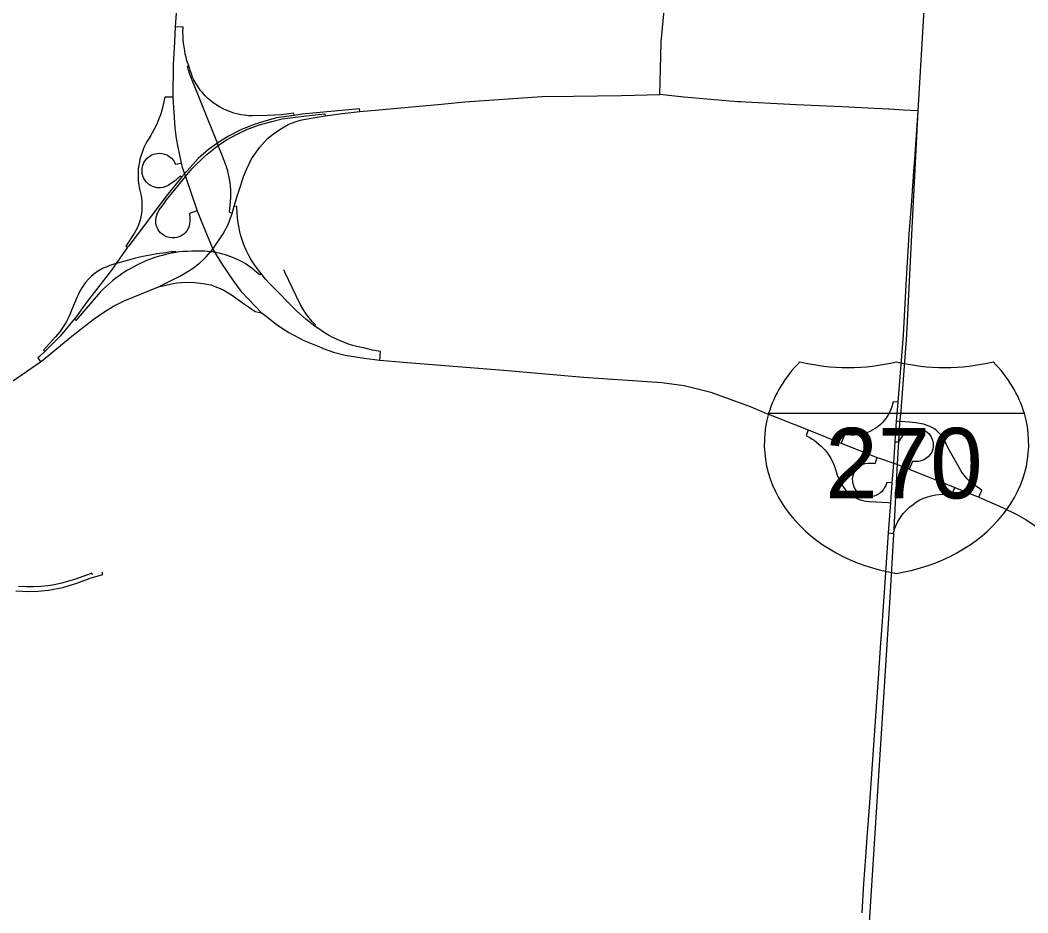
# Model space of a CAD drawing. Extents: x -1146 to -445, y -1283 to -822.
# Drawn here: x -822.31 to -786.59, y -1035.57 to -1003.92 of the extents above; entities that cross this region are included whole.
import ezdxf

# ---------------------------------------------------------------- set-up
doc = ezdxf.new("R2010")
doc.units = 0
for name, color, linetype in [('GM_X_Interchange_Ramps', 7, 'Continuous'), ('GM_X_Interstate_Route', 7, 'Continuous'), ('GM_X_Interstate_Shield', 7, 'Continuous'), ('GM_X_State_Route', 7, 'Continuous'), ('GM_X_Township', 7, 'Continuous'), ('GM_X_US_Route', 7, 'Continuous')]:
    doc.layers.add(name, color=color, linetype=linetype)

msp = doc.modelspace()

# ---------------------------------------------------------------- linework, layer by layer
at = {"layer": 'GM_X_Interchange_Ramps'}
for points in [[(-812.59, -1007.298), (-812.601, -1007.222), (-813.047, -1007.28), (-813.536, -1007.297), (-814.066, -1007.313), (-814.216, -1007.309), (-814.35, -1007.296), (-814.488, -1007.276), (-814.632, -1007.244), (-814.735, -1007.216), (-814.857, -1007.176), (-815.002, -1007.119), (-815.09, -1007.078), (-815.241, -1006.998), (-815.371, -1006.917), (-815.467, -1006.848), (-815.566, -1006.77), (-815.663, -1006.684), (-815.747, -1006.602), (-815.846, -1006.493), (-815.922, -1006.399), (-816.002, -1006.287), (-816.071, -1006.179), (-816.146, -1006.044), (-816.195, -1005.941), (-816.238, -1005.825), (-816.281, -1005.703), (-816.308, -1005.618), (-816.329, -1005.548), (-816.332, -1005.539), (-816.394, -1005.363), (-816.428, -1005.238), (-816.453, -1005.124), (-816.476, -1005.008), (-816.499, -1004.868), (-816.517, -1004.74), (-816.529, -1004.608), (-816.534, -1004.494), (-816.536, -1004.35), (-816.534, -1004.176), (-816.811, -1004.161)], [(-814.788, -1010.776), (-814.891, -1010.73), (-814.852, -1010.368), (-814.842, -1010.206), (-814.84, -1010.072), (-814.843, -1009.951), (-814.854, -1009.796), (-814.868, -1009.673), (-814.885, -1009.562), (-814.907, -1009.445), (-814.929, -1009.345), (-814.951, -1009.261), (-814.992, -1009.123), (-815.133, -1008.749), (-815.284, -1008.371), (-815.316, -1008.289), (-816.302, -1005.812), (-816.338, -1005.699), (-816.378, -1005.552), (-816.329, -1005.548)], [(-816.894, -1006.654), (-817.179, -1006.653), (-817.269, -1007.076), (-817.3, -1007.166), (-817.337, -1007.284), (-817.39, -1007.423), (-817.444, -1007.551), (-817.504, -1007.682), (-817.57, -1007.813), (-817.627, -1007.916), (-817.679, -1008.007), (-817.763, -1008.138), (-817.804, -1008.207), (-817.852, -1008.294), (-817.9, -1008.391), (-817.937, -1008.473), (-817.977, -1008.575), (-818.023, -1008.711), (-818.062, -1008.85), (-818.083, -1008.95), (-818.11, -1009.11), (-818.121, -1009.217), (-818.128, -1009.34), (-818.13, -1009.438), (-818.126, -1009.559), (-818.121, -1009.631), (-818.106, -1009.758), (-818.091, -1009.852), (-818.068, -1009.958), (-818.041, -1010.059), (-818.022, -1010.151), (-818.009, -1010.23), (-817.997, -1010.332), (-817.991, -1010.431), (-817.99, -1010.55), (-817.996, -1010.653), (-818.009, -1010.773), (-818.03, -1010.893), (-818.056, -1011.004), (-818.085, -1011.102), (-818.11, -1011.173), (-818.152, -1011.275), (-818.268, -1011.487), (-818.559, -1011.934), (-818.5, -1011.975)], [(-810.27, -1007.162), (-810.275, -1007.064), (-812.308, -1007.257), (-812.59, -1007.298), (-813.222, -1007.39), (-813.666, -1007.515), (-814.048, -1007.63), (-814.483, -1007.808), (-814.927, -1008.039), (-815.238, -1008.234), (-815.316, -1008.289), (-815.629, -1008.509), (-816.002, -1008.829), (-816.484, -1009.368), (-816.592, -1009.489), (-816.669, -1009.591), (-817.129, -1010.161), (-817.866, -1011.139), (-818.461, -1011.92), (-818.5, -1011.975), (-818.91, -1012.551), (-819.074, -1012.782), (-819.607, -1013.466), (-819.971, -1013.945), (-820.326, -1014.443), (-820.391, -1014.521), (-820.619, -1014.798), (-820.894, -1015.127), (-821.276, -1015.518), (-821.432, -1015.666), (-821.623, -1015.846), (-821.686, -1015.893), (-821.586, -1016.03)], [(-816.033, -1010.68), (-816.307, -1010.774), (-816.295, -1010.957), (-816.29, -1011.049), (-816.3, -1011.147), (-816.321, -1011.23), (-816.354, -1011.309), (-816.402, -1011.39), (-816.458, -1011.457), (-816.508, -1011.504), (-816.595, -1011.564), (-816.673, -1011.602), (-816.76, -1011.629), (-816.84, -1011.642), (-816.924, -1011.644), (-817.029, -1011.63), (-817.122, -1011.602), (-817.205, -1011.561), (-817.276, -1011.512), (-817.328, -1011.465), (-817.379, -1011.407), (-817.415, -1011.355), (-817.457, -1011.272), (-817.482, -1011.201), (-817.499, -1011.116), (-817.504, -1011.032), (-817.49, -1010.908), (-817.457, -1010.796), (-817.379, -1010.647), (-817.28, -1010.515), (-817.126, -1010.287), (-816.746, -1009.828), (-816.449, -1009.47), (-816.225, -1009.199), (-815.741, -1008.719), (-815.381, -1008.437), (-815.284, -1008.371), (-814.988, -1008.169), (-814.615, -1007.962), (-814.247, -1007.788), (-813.829, -1007.639), (-813.391, -1007.515), (-813.019, -1007.424), (-812.551, -1007.362), (-812.16, -1007.32), (-811.835, -1007.277), (-811.511, -1007.246), (-811.501, -1007.311)], [(-816.592, -1009.489), (-816.634, -1009.455), (-816.833, -1009.629), (-817.064, -1009.782), (-817.15, -1009.824), (-817.239, -1009.852), (-817.331, -1009.865), (-817.449, -1009.863), (-817.58, -1009.832), (-817.691, -1009.779), (-817.758, -1009.733), (-817.829, -1009.666), (-817.877, -1009.606), (-817.92, -1009.536), (-817.959, -1009.441), (-817.978, -1009.365), (-817.988, -1009.273), (-817.983, -1009.174), (-817.961, -1009.073), (-817.92, -1008.973), (-817.866, -1008.887), (-817.808, -1008.82), (-817.744, -1008.765), (-817.666, -1008.714), (-817.58, -1008.676), (-817.515, -1008.657), (-817.451, -1008.646), (-817.359, -1008.641), (-817.287, -1008.647), (-817.186, -1008.671), (-817.109, -1008.702), (-817.036, -1008.743), (-816.986, -1008.781), (-816.949, -1008.814), (-816.874, -1008.901), (-816.797, -1009.032), (-816.606, -1008.988)], [(-809.56, -1015.977), (-809.529, -1015.665), (-809.813, -1015.621), (-810.092, -1015.556), (-810.206, -1015.529), (-810.368, -1015.493), (-810.514, -1015.453), (-810.668, -1015.405), (-810.811, -1015.355), (-810.967, -1015.292), (-811.119, -1015.224), (-811.245, -1015.162), (-811.376, -1015.091), (-811.52, -1015.005), (-811.69, -1014.894), (-811.846, -1014.78), (-811.864, -1014.766), (-812.184, -1014.521), (-812.512, -1014.227), (-813.449, -1013.281), (-813.615, -1013.1), (-813.762, -1012.902), (-813.899, -1012.737), (-813.994, -1012.605), (-814.066, -1012.494), (-814.14, -1012.372), (-814.213, -1012.24), (-814.28, -1012.104), (-814.341, -1011.966), (-814.389, -1011.847), (-814.437, -1011.712), (-814.481, -1011.568), (-814.519, -1011.424), (-814.55, -1011.288), (-814.573, -1011.162), (-814.591, -1011.035), (-814.605, -1010.907), (-814.615, -1010.77), (-814.625, -1010.529), (-814.721, -1010.511)], [(-816.788, -1012.157), (-816.793, -1012.126), (-816.858, -1012.133), (-816.929, -1012.14), (-817.034, -1012.152), (-817.144, -1012.166), (-817.234, -1012.178), (-817.356, -1012.195), (-817.461, -1012.212), (-817.57, -1012.23), (-817.703, -1012.253), (-817.831, -1012.278), (-817.955, -1012.304), (-818.071, -1012.329), (-818.263, -1012.374), (-818.423, -1012.415), (-818.727, -1012.496), (-818.857, -1012.534), (-818.91, -1012.551), (-818.986, -1012.576), (-819.13, -1012.625), (-819.259, -1012.674), (-819.369, -1012.718), (-819.511, -1012.796), (-819.633, -1012.88), (-819.718, -1012.946), (-819.796, -1013.015), (-819.886, -1013.105), (-819.992, -1013.227), (-820.049, -1013.303), (-820.121, -1013.409), (-820.188, -1013.525), (-820.245, -1013.642), (-820.285, -1013.736), (-820.482, -1014.178), (-820.545, -1014.357), (-820.604, -1014.486), (-820.666, -1014.604), (-820.736, -1014.725), (-820.907, -1014.977), (-821.05, -1015.151), (-821.475, -1015.621), (-821.432, -1015.666)], [(-813.762, -1012.902), (-813.809, -1012.946), (-813.913, -1012.866), (-813.996, -1012.796), (-814.088, -1012.724), (-814.17, -1012.664), (-814.246, -1012.612), (-814.337, -1012.555), (-814.439, -1012.495), (-814.533, -1012.445), (-814.644, -1012.391), (-814.74, -1012.348), (-814.844, -1012.307), (-814.934, -1012.274), (-815.025, -1012.245), (-815.126, -1012.216), (-815.248, -1012.185), (-815.366, -1012.161), (-815.408, -1012.154), (-815.488, -1012.141), (-815.557, -1012.133), (-815.663, -1012.121), (-815.767, -1012.114), (-815.917, -1012.11), (-816.102, -1012.111), (-816.22, -1012.112), (-816.387, -1012.119), (-816.528, -1012.129), (-816.649, -1012.14), (-816.788, -1012.157), (-816.949, -1012.186), (-817.053, -1012.208), (-817.148, -1012.23), (-817.265, -1012.26), (-817.381, -1012.292), (-817.536, -1012.341), (-817.689, -1012.395), (-817.826, -1012.448), (-817.95, -1012.501), (-818.05, -1012.546), (-818.178, -1012.609), (-818.282, -1012.663), (-818.39, -1012.723), (-818.499, -1012.787), (-818.601, -1012.85), (-818.7, -1012.915), (-818.814, -1012.995), (-818.935, -1013.085), (-819.036, -1013.165), (-819.147, -1013.257), (-819.248, -1013.347), (-819.37, -1013.463), (-819.477, -1013.571), (-820.339, -1014.564), (-820.391, -1014.521)], [(-811.864, -1014.766), (-811.833, -1014.725), (-811.962, -1014.609), (-812.067, -1014.481), (-812.161, -1014.356), (-812.264, -1014.186), (-812.38, -1013.987), (-812.927, -1012.852), (-812.965, -1012.776)], [(-791.184, -1017.468), (-791.362, -1017.458), (-791.413, -1017.634), (-791.448, -1017.73), (-791.492, -1017.828), (-791.555, -1017.941), (-791.622, -1018.041), (-791.693, -1018.129), (-791.753, -1018.195), (-791.813, -1018.253), (-791.894, -1018.322), (-791.996, -1018.395), (-792.081, -1018.448), (-792.185, -1018.501), (-792.299, -1018.548), (-792.408, -1018.583), (-792.519, -1018.609), (-792.635, -1018.627), (-792.733, -1018.634), (-792.849, -1018.635), (-793.08, -1018.619), (-793.201, -1018.92)], [(-791.287, -1018.868), (-791.162, -1018.876), (-791.058, -1018.701), (-790.998, -1018.626), (-790.93, -1018.557), (-790.852, -1018.496), (-790.797, -1018.461), (-790.711, -1018.421), (-790.59, -1018.395), (-790.471, -1018.393), (-790.376, -1018.41), (-790.238, -1018.466), (-790.15, -1018.526), (-790.084, -1018.591), (-790.013, -1018.689), (-789.963, -1018.806), (-789.939, -1018.924), (-789.938, -1019.019), (-789.958, -1019.135), (-789.994, -1019.233), (-790.047, -1019.323), (-790.108, -1019.395), (-790.176, -1019.454), (-790.275, -1019.513), (-790.372, -1019.548), (-790.455, -1019.565), (-790.678, -1019.57), (-790.791, -1019.839)], [(-788.32, -1020.835), (-788.213, -1020.584), (-788.41, -1020.454), (-788.505, -1020.389), (-788.593, -1020.32), (-788.661, -1020.259), (-788.733, -1020.187), (-788.801, -1020.11), (-788.849, -1020.05), (-788.901, -1019.977), (-788.956, -1019.891), (-789.419, -1019.071), (-789.476, -1018.942), (-789.539, -1018.815), (-789.593, -1018.731), (-789.661, -1018.64), (-789.728, -1018.561), (-789.809, -1018.48), (-789.896, -1018.411), (-790.008, -1018.35), (-790.09, -1018.313), (-790.186, -1018.276), (-790.271, -1018.249), (-790.359, -1018.227), (-790.482, -1018.205), (-790.566, -1018.196), (-790.783, -1018.179), (-791.115, -1018.149), (-791.135, -1018.147), (-791.238, -1018.138)], [(-794.372, -1018.451), (-794.449, -1018.643), (-794.317, -1018.717), (-794.23, -1018.771), (-794.162, -1018.817), (-794.076, -1018.881), (-793.993, -1018.948), (-793.913, -1019.021), (-793.842, -1019.092), (-793.785, -1019.154), (-793.725, -1019.224), (-793.66, -1019.309), (-793.591, -1019.412), (-793.534, -1019.517), (-793.471, -1019.656), (-793.43, -1019.764), (-793.342, -1020.053), (-793.286, -1020.188), (-793.238, -1020.286), (-793.176, -1020.394), (-793.119, -1020.481), (-793.061, -1020.561), (-792.968, -1020.672), (-792.885, -1020.75), (-792.781, -1020.815), (-792.674, -1020.87), (-792.564, -1020.915), (-792.435, -1020.951), (-792.335, -1020.973), (-792.199, -1020.989), (-791.542, -1021.027), (-791.449, -1021.038)], [(-791.391, -1020.33), (-791.58, -1020.31), (-791.624, -1020.416), (-791.665, -1020.495), (-791.708, -1020.565), (-791.776, -1020.647), (-791.856, -1020.714), (-791.947, -1020.765), (-792.04, -1020.799), (-792.185, -1020.82), (-792.299, -1020.812), (-792.378, -1020.793), (-792.456, -1020.762), (-792.514, -1020.731), (-792.585, -1020.679), (-792.667, -1020.595), (-792.741, -1020.476), (-792.771, -1020.401), (-792.795, -1020.284), (-792.797, -1020.174), (-792.779, -1020.065), (-792.753, -1019.988), (-792.704, -1019.895), (-792.633, -1019.805), (-792.543, -1019.727), (-792.461, -1019.679), (-792.349, -1019.638), (-792.245, -1019.625), (-792.146, -1019.623), (-792.059, -1019.629), (-792.002, -1019.639), (-791.922, -1019.432)], [(-791.527, -1022.102), (-791.366, -1022.115), (-791.328, -1022.015), (-791.296, -1021.93), (-791.195, -1021.699), (-791.097, -1021.552), (-791.004, -1021.415), (-790.897, -1021.305), (-790.772, -1021.18), (-790.656, -1021.087), (-790.535, -1021.001), (-790.419, -1020.931), (-790.306, -1020.879), (-790.173, -1020.83), (-790.019, -1020.789), (-789.851, -1020.752), (-789.627, -1020.726), (-789.469, -1020.731), (-789.286, -1020.752), (-789.175, -1020.491)], [(-822.463, -1024.155), (-822.001, -1024.177), (-821.676, -1024.164), (-821.305, -1024.129), (-820.793, -1024.031), (-820.303, -1023.876), (-819.829, -1023.703), (-819.381, -1023.571), (-819.402, -1023.493)], [(-819.743, -1023.59), (-819.764, -1023.529), (-819.888, -1023.572), (-820.383, -1023.747), (-820.839, -1023.883), (-821.09, -1023.936), (-821.33, -1023.974), (-821.58, -1023.998), (-821.833, -1024.012), (-822.084, -1024.014), (-822.37, -1023.999)]]:
    msp.add_lwpolyline(points, dxfattribs=at)
at = {"layer": 'GM_X_Interstate_Route'}
for points in [[(-816.557, -1000.485), (-816.614, -1001.423), (-816.811, -1004.161)], [(-816.811, -1004.161), (-816.853, -1004.927), (-816.884, -1005.488), (-816.894, -1006.654), (-816.822, -1007.741), (-816.776, -1008.121), (-816.719, -1008.421), (-816.606, -1008.988), (-816.56, -1009.129)], [(-816.56, -1009.129), (-816.484, -1009.368), (-816.477, -1009.388), (-816.449, -1009.47), (-816.033, -1010.68)], [(-816.033, -1010.68), (-815.867, -1011.092), (-815.477, -1012.039)], [(-815.477, -1012.039), (-815.408, -1012.154), (-815.17, -1012.551), (-814.742, -1013.18), (-814.487, -1013.532), (-814.195, -1013.842), (-813.747, -1014.297)], [(-821.586, -1016.03), (-821.493, -1015.959), (-820.537, -1015.17), (-819.718, -1014.53), (-819.343, -1014.27), (-819.001, -1014.06), (-818.625, -1013.872), (-817.402, -1013.375)], [(-817.402, -1013.375), (-816.884, -1013.258), (-816.76, -1013.232), (-816.585, -1013.218), (-816.414, -1013.215), (-816.127, -1013.218), (-815.92, -1013.242), (-815.765, -1013.266), (-815.552, -1013.311), (-815.369, -1013.373), (-815.345, -1013.383)], [(-815.345, -1013.383), (-815.217, -1013.435), (-815.087, -1013.497), (-814.776, -1013.681), (-814.351, -1013.986), (-814.184, -1014.111), (-813.98, -1014.246), (-813.747, -1014.297)], [(-813.747, -1014.297), (-813.747, -1014.297), (-813.638, -1014.382), (-813.475, -1014.511)], [(-813.475, -1014.511), (-813.47, -1014.514), (-813.291, -1014.65)], [(-813.291, -1014.65), (-813.184, -1014.732), (-812.785, -1014.996), (-812.253, -1015.278), (-811.603, -1015.543), (-811.563, -1015.558)], [(-811.563, -1015.558), (-811.203, -1015.693), (-810.782, -1015.8), (-810.111, -1015.907), (-809.56, -1015.977)], [(-832.702, -1024.238), (-832.582, -1024.136), (-831.784, -1023.485), (-830.941, -1022.774), (-829.758, -1021.831), (-829.625, -1021.723), (-829.525, -1021.642), (-828.622, -1020.976), (-827.677, -1020.291), (-825.937, -1019.089), (-824.334, -1017.972), (-822.58, -1016.719), (-821.586, -1016.03)], [(-809.56, -1015.977), (-808.715, -1016.045), (-807.256, -1016.164), (-805.157, -1016.335), (-802.34, -1016.579), (-799.559, -1016.769), (-798.765, -1016.878), (-797.829, -1017.105), (-796.434, -1017.616), (-795.848, -1017.868), (-795.839, -1017.872)], [(-795.839, -1017.872), (-794.372, -1018.451), (-793.201, -1018.92), (-791.922, -1019.432), (-791.34, -1019.627)], [(-791.34, -1019.627), (-791.204, -1019.679), (-790.791, -1019.839), (-789.175, -1020.491), (-788.32, -1020.835), (-787.49, -1021.194), (-786.976, -1021.447), (-786.651, -1021.637), (-786.378, -1021.818), (-786.128, -1022.019), (-785.909, -1022.199), (-785.61, -1022.472), (-785.107, -1023.027), (-784.779, -1023.449), (-784.514, -1023.836), (-784.367, -1024.072), (-784.257, -1024.247), (-783.97, -1024.791), (-783.806, -1025.17), (-783.729, -1025.389)]]:
    msp.add_lwpolyline(points, dxfattribs=at)
at = {"layer": 'GM_X_Interstate_Shield'}
msp.add_line((-786.71, -1017.869), (-795.775, -1017.869), dxfattribs=at)
msp.add_line((-786.71, -1017.869), (-795.775, -1017.869), dxfattribs=at)
for centre, start_param, end_param in [((-790.071, -1018.941), 2.47259, 2.911027), ((-792.955, -1011.55), 4.415841, 5.008937), ((-789.53, -1011.55), 4.415841, 5.008937), ((-792.414, -1018.941), 0.230566, 0.669003), ((-790.071, -1018.941), 2.911027, 4.511031), ((-792.414, -1018.941), 4.913747, 6.513751)]:
    msp.add_ellipse(centre, major_axis=(5.859, 0), ratio=0.8, start_param=start_param, end_param=end_param, dxfattribs=at)
at = {"layer": 'GM_X_State_Route'}
for points in [[(-796.763, -1006.824), (-796.874, -1006.817), (-798.781, -1006.649), (-799.635, -1006.554)], [(-794.798, -1006.922), (-796.595, -1006.835), (-796.763, -1006.824)], [(-791.524, -1007.081), (-792.033, -1007.056), (-793.165, -1007.001), (-794.798, -1006.922)], [(-791, -1007.108), (-791.505, -1007.082), (-791.524, -1007.081)], [(-790.477, -1007.136), (-790.477, -1007.136), (-791, -1007.108)], [(-790.608, -1009.011), (-790.477, -1007.136)], [(-790.895, -1013.3), (-790.794, -1011.512), (-790.712, -1010.498), (-790.615, -1009.114), (-790.608, -1009.011)], [(-790.996, -1015.088), (-790.895, -1013.3)], [(-791.227, -1018.004), (-791.184, -1017.468), (-790.996, -1015.088)], [(-791.34, -1019.627), (-791.287, -1018.868), (-791.238, -1018.138), (-791.227, -1018.004)], [(-791.717, -1024.864), (-791.685, -1024.375), (-791.527, -1022.102), (-791.449, -1021.038), (-791.391, -1020.33), (-791.34, -1019.627)], [(-791.794, -1025.994), (-791.753, -1025.407), (-791.717, -1024.864)], [(-791.883, -1027.25), (-791.794, -1025.994)], [(-792.286, -1032.899), (-792.193, -1031.654), (-791.883, -1027.25)], [(-792.465, -1035.568), (-792.4, -1034.529), (-792.335, -1033.579), (-792.286, -1032.899)]]:
    msp.add_lwpolyline(points, dxfattribs=at)
at = {"layer": 'GM_X_Township'}
msp.add_lwpolyline([(-792.543, -1041.281), (-791.464, -1024.391), (-791.324, -1021.951), (-791.203, -1019.653), (-791.162, -1018.876), (-791.123, -1018.205), (-791.072, -1017.772), (-790.875, -1015.08), (-790.697, -1011.518), (-790.477, -1007.136), (-790.244, -1003.355)], dxfattribs=at)
at = {"layer": 'GM_X_US_Route'}
for points in [[(-799.635, -1006.554), (-799.608, -1005.655), (-799.582, -1004.701), (-799.508, -1003.816), (-799.441, -1003.335)], [(-808.164, -1006.968), (-807.374, -1006.896), (-806.542, -1006.822), (-803.811, -1006.635), (-802.69, -1006.612), (-800.988, -1006.589), (-799.635, -1006.554)], [(-814.605, -1010.128), (-814.562, -1009.985), (-814.383, -1009.447), (-814.283, -1009.218), (-814.104, -1008.839), (-813.815, -1008.421), (-813.542, -1008.117), (-813.333, -1007.947), (-813.073, -1007.771), (-812.805, -1007.621), (-812.688, -1007.569), (-812.492, -1007.504), (-812.323, -1007.458), (-811.991, -1007.394), (-811.501, -1007.311), (-810.89, -1007.227), (-810.27, -1007.162), (-809.597, -1007.098), (-808.164, -1006.968)], [(-815.834, -1012.426), (-815.709, -1012.312), (-815.557, -1012.133), (-815.477, -1012.039), (-815.109, -1011.495), (-814.937, -1011.167), (-814.788, -1010.776), (-814.721, -1010.511), (-814.605, -1010.128)], [(-817.402, -1013.375), (-816.653, -1013.001), (-816.333, -1012.813), (-816.132, -1012.679), (-816.033, -1012.598)], [(-816.033, -1012.598), (-815.942, -1012.524), (-815.834, -1012.426)]]:
    msp.add_lwpolyline(points, dxfattribs=at)

# ---------------------------------------------------------------- texts
at = {"layer": 'GM_X_Interstate_Shield'}
msp.add_text('270', height=2.5, dxfattribs=at).set_placement((-793.767, -1020.877))

doc.saveas('drawing.dxf')
